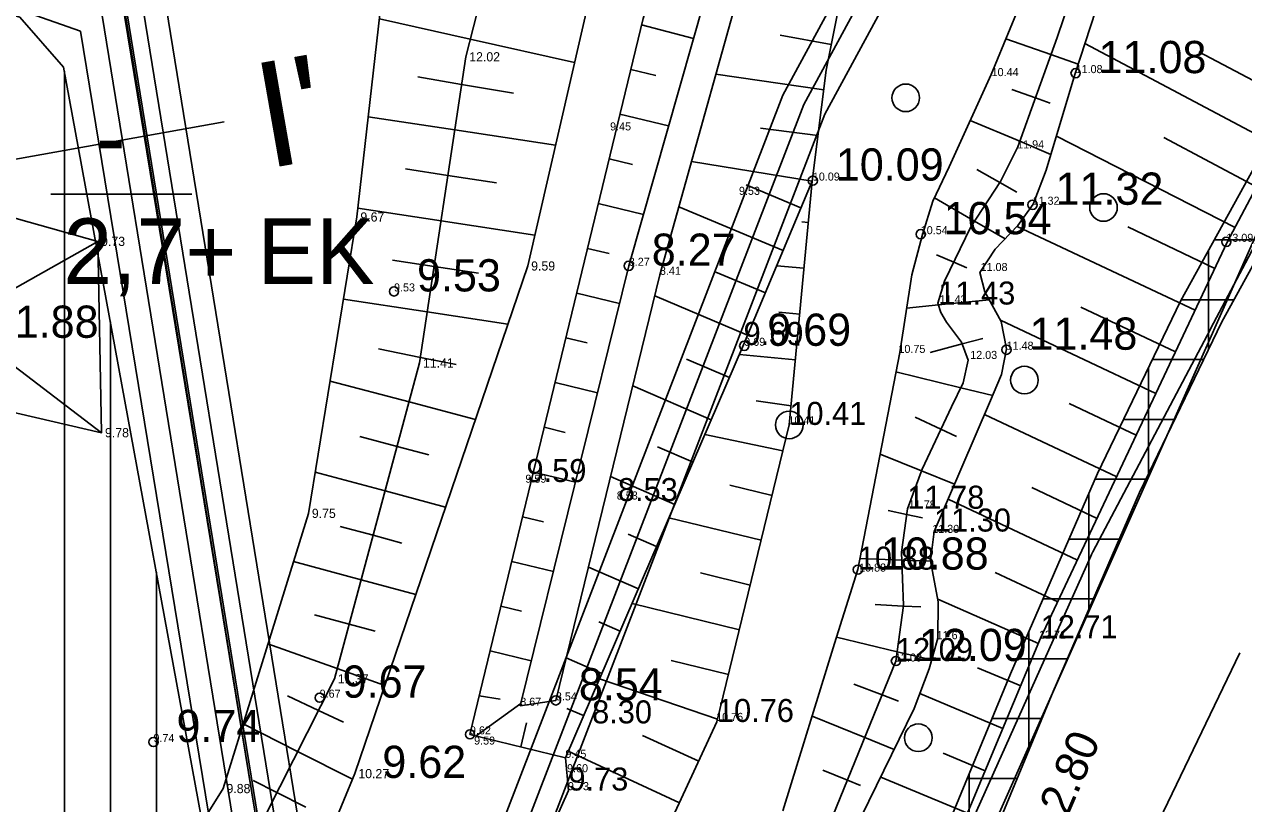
# Model space of a CAD drawing. Extents: x 433497 to 434382, y 6534486 to 6534993.
# Drawn here: x 434123.5 to 434176.5, y 6534820.5 to 6534854.4 of the extents above; entities that cross this region are included whole.
import ezdxf

# ---------------------------------------------------------------- set-up
doc = ezdxf.new("R2010")
doc.units = 0
for name, color, linetype in [('Default', 7, 'Continuous'), ('GEOLPUNKT', 7, 'Continuous'), ('HALJASTUS', 7, 'Continuous'), ('Kaitsevöönd', 7, 'Continuous'), ('kataster', 7, 'Continuous'), ('KORGUS-EH2000', 7, 'Continuous'), ('l__x00e4__bil__x00f5__iked', 7, 'Continuous'), ('MAAMUDEL-EH2000', 7, 'Continuous'), ('MOOTKORG-EH2000', 7, 'Continuous'), ('PIIR', 7, 'Continuous'), ('RELJEEF', 7, 'Continuous'), ('TEE', 7, 'Continuous'), ('Täide', 7, 'Continuous'), ('VEEKOGU', 7, 'Continuous')]:
    doc.layers.add(name, color=color, linetype=linetype)

msp = doc.modelspace()

# ---------------------------------------------------------------- linework, layer by layer
at = {"layer": 'Default'}
msp.add_lwpolyline([(433617.12, 6534791.025), (433632.75, 6534606.045), (434137.38, 6534796.515), (434127.69, 6534855.6), (433968.21, 6534911.925), (433942.38, 6534904.035), (433920.99, 6534907.275)], close=True, dxfattribs=at)
msp.add_lwpolyline([(433617.12, 6534791.025), (433632.75, 6534606.045), (434137.38, 6534796.515), (434127.69, 6534855.6), (433968.21, 6534911.925), (433942.38, 6534904.035), (433920.99, 6534907.275)], close=True, dxfattribs=at)
msp.add_lwpolyline([(433617.12, 6534791.025), (433632.75, 6534606.045), (434137.38, 6534796.515), (434127.69, 6534855.6), (433968.21, 6534911.925), (433942.38, 6534904.035), (433920.99, 6534907.275)], close=True, dxfattribs=at)
at = {"layer": 'GEOLPUNKT'}
msp.add_lwpolyline([(434124.622, 6534847.029), (434130.749, 6534847.029)], dxfattribs=at)
at = {"layer": 'HALJASTUS'}
msp.add_lwpolyline([(434176.296, 6534827.099), (434172.063, 6534818.302), (434169.946, 6534813.21), (434168.822, 6534810.233), (434168.64, 6534809.811), (434168.425, 6534809.332), (434168.425, 6534809.067), (434168.491, 6534808.72), (434168.468, 6534808.536), (434169.037, 6534808.042), (434171.153, 6534807.166), (434175.419, 6534805.557), (434176.131, 6534805.38), (434178.214, 6534804.983), (434182.414, 6534804.586), (434188.202, 6534804.421), (434190.149, 6534804.398), (434193.758, 6534804.388)], dxfattribs=at)
for centre in [(434161.779, 6534851.217), (434170.372, 6534846.452), (434166.935, 6534838.952), (434156.717, 6534837.003), (434162.326, 6534823.407)]:
    msp.add_circle(centre, 0.6, dxfattribs=at)
at = {"layer": 'Kaitsevöönd'}
for p, q in [((434175.189, 6534845.039), (434177.471, 6534845.039)), ((434174.931, 6534840.28), (434174.931, 6534844.571)), ((434173.755, 6534842.439), (434176.037, 6534842.439)), ((434172.331, 6534834.881), (434172.331, 6534839.489)), ((434172.499, 6534839.839), (434174.718, 6534839.839)), ((434171.247, 6534837.239), (434173.466, 6534837.239)), ((434170.007, 6534834.639), (434172.214, 6534834.639)), ((434169.731, 6534828.979), (434169.731, 6534834.002)), ((434168.879, 6534832.039), (434171.059, 6534832.039)), ((434167.751, 6534829.439), (434169.93, 6534829.439)), ((434167.131, 6534822.87), (434167.131, 6534828.01)), ((434166.623, 6534826.839), (434168.802, 6534826.839)), ((434165.534, 6534824.239), (434167.697, 6534824.239)), ((434164.458, 6534821.639), (434166.621, 6534821.639)), ((434164.531, 6534816.587), (434164.531, 6534821.816))]:
    msp.add_line(p, q, dxfattribs=at)
for points in [[(434128.222, 6534730.093), (434132.174, 6534738.642), (434136.032, 6534747.247), (434138.365, 6534752.329), (434142.93, 6534762.753), (434145.458, 6534769.142), (434146.369, 6534771.613), (434148.646, 6534776.777), (434150.916, 6534781.958), (434153.219, 6534787.206), (434154.721, 6534791.754), (434156.628, 6534795.899), (434159.877, 6534804.556), (434163.808, 6534814.841), (434168.182, 6534825.411), (434171.941, 6534834.072), (434175.51, 6534841.483), (434180.59, 6534850.694), (434185.974, 6534861.252), (434188.694, 6534866.232), (434193.777, 6534875.182), (434200.729, 6534887.95), (434203.323, 6534892.681)], [(434198.974, 6534888.909), (434192.024, 6534876.146), (434186.943, 6534867.198), (434184.199, 6534862.173), (434178.816, 6534851.617), (434173.72, 6534842.375), (434170.114, 6534834.886), (434166.338, 6534826.183), (434161.945, 6534815.568), (434158.005, 6534805.262), (434154.768, 6534796.635), (434152.881, 6534792.54), (434152.839, 6534792.435), (434151.335, 6534787.878), (434149.085, 6534782.762), (434146.815, 6534777.582), (434144.503, 6534772.334), (434143.585, 6534769.845), (434141.077, 6534763.506), (434136.537, 6534753.14), (434134.209, 6534748.069), (434130.352, 6534739.465)]]:
    msp.add_lwpolyline(points, dxfattribs=at)
at = {"layer": 'kataster'}
msp.add_lwpolyline([(433617.102, 6534791.002), (433632.769, 6534606.029), (434137.446, 6534796.469), (434127.827, 6534855.589), (433950.026, 6534918.39)], close=True, dxfattribs=at)
msp.add_lwpolyline([(434117.185, 6534708.296), (434124.427, 6534725.502), (434148.55, 6534781.242), (434178.983, 6534849.691), (434202.394, 6534892.23)], dxfattribs=at)
at = {"layer": 'KORGUS-EH2000'}
for centre in [(434169.16, 6534852.29), (434157.74, 6534847.62), (434167.29, 6534846.57), (434162.43, 6534845.29), (434175.71, 6534844.96), (434149.741, 6534843.917), (434139.54, 6534842.804), (434154.76, 6534840.44), (434166.16, 6534840.27), (434159.697, 6534830.713), (434161.352, 6534826.741), (434136.307, 6534825.149), (434146.573, 6534825.031), (434142.84, 6534823.556), (434129.085, 6534823.221)]:
    msp.add_circle(centre, 0.2, dxfattribs=at)
at = {"layer": 'l__x00e4__bil__x00f5__iked'}
msp.add_lwpolyline([(433620.07, 6534691.039), (433627.105, 6534692.187), (433736.834, 6534712.709), (433742.792, 6534710.723), (433822.234, 6534766.498), (433986.579, 6534812.177), (434120.472, 6534848.091), (434132.163, 6534850.175)], dxfattribs=at)
at = {"layer": 'PIIR'}
for points in [[(434138.342, 6534801.592), (434129.36, 6534856.88), (433968.248, 6534913.871)], [(433632.021, 6534604.835), (434138.248, 6534795.936), (434128.468, 6534856.135), (433968.226, 6534912.818), (433942.33, 6534904.85), (433920.952, 6534908.165), (433616.327, 6534791.524), (433632.021, 6534604.835)], [(433632.732, 6534605.959), (434137.353, 6534796.454), (434127.754, 6534855.539), (433968.208, 6534911.976), (433942.39, 6534904.031), (433921.04, 6534907.341), (433617.174, 6534790.992), (433632.732, 6534605.959)], [(434137.312, 6534801.699), (434156.44, 6534851.34), (434184.392, 6534902.877)], [(434138.342, 6534801.592), (434157.35, 6534850.92), (434185.271, 6534902.4)], [(434138.358, 6534798.853), (434158.26, 6534850.5), (434186.15, 6534901.923)]]:
    msp.add_lwpolyline(points, dxfattribs=at)
for points in [[(433618.234, 6534790.327), (433921.149, 6534906.313), (433942.464, 6534903.008), (433968.187, 6534910.923), (434126.862, 6534854.794), (434136.235, 6534797.101), (433633.617, 6534607.362)], [(433619.24, 6534789.695), (433634.52, 6534608.851), (434135.141, 6534797.808), (434125.908, 6534854.108), (433968.165, 6534909.82), (433942.53, 6534901.99), (433921.212, 6534905.219)], [(433619.24, 6534789.695), (433634.52, 6534608.851), (434135.141, 6534797.808), (434125.908, 6534854.108), (433968.165, 6534909.82), (433942.53, 6534901.99), (433921.212, 6534905.219)]]:
    msp.add_lwpolyline(points, close=True, dxfattribs=at)
at = {"layer": 'RELJEEF'}
for p, q in [((434142.855, 6534853.763), (434138.905, 6534854.647)), ((434150.299, 6534854.394), (434152.549, 6534853.793)), ((434156.328, 6534853.942), (434158.543, 6534853.534)), ((434168.088, 6534853.094), (434166.129, 6534853.788)), ((434142.855, 6534853.763), (434147.383, 6534852.751)), ((434177.965, 6534849.122), (434169.567, 6534853.577)), ((434168.088, 6534853.094), (434169.274, 6534852.673)), ((434174.522, 6534853.213), (434178.903, 6534850.889)), ((434150.923, 6534852.186), (434149.829, 6534852.451)), ((434158.212, 6534851.563), (434153.528, 6534852.252)), ((434140.568, 6534852.129), (434142.479, 6534851.802)), ((434144.733, 6534851.415), (434142.479, 6534851.802)), ((434166.387, 6534851.58), (434167.412, 6534851.211)), ((434168.05, 6534850.982), (434167.412, 6534851.211)), ((434142.18, 6534849.824), (434138.423, 6534850.392)), ((434149.359, 6534850.507), (434151.469, 6534849.996)), ((434166.736, 6534849.329), (434164.584, 6534850.235)), ((434142.18, 6534849.824), (434146.558, 6534849.162)), ((434155.46, 6534849.895), (434157.961, 6534849.579)), ((434176.091, 6534845.589), (434168.329, 6534849.557)), ((434166.736, 6534849.329), (434168.09, 6534848.759)), ((434172.991, 6534849.497), (434177.028, 6534847.356)), ((434149.905, 6534848.317), (434148.888, 6534848.563)), ((434140.039, 6534848.125), (434141.881, 6534847.847)), ((434157.71, 6534847.595), (434152.467, 6534848.448)), ((434164.866, 6534848.097), (434165.863, 6534847.532)), ((434143.995, 6534847.527), (434141.881, 6534847.847)), ((434154.843, 6534847.43), (434157.224, 6534846.433)), ((434157.71, 6534847.595), (434157.71, 6534847.595)), ((434166.604, 6534847.112), (434165.863, 6534847.532)), ((434141.582, 6534845.869), (434137.972, 6534846.415)), ((434148.418, 6534846.619), (434150.375, 6534846.146)), ((434156.452, 6534844.588), (434151.92, 6534846.485)), ((434164.769, 6534845.858), (434163.026, 6534846.864)), ((434141.582, 6534845.869), (434145.659, 6534845.253)), ((434157.263, 6534845.829), (434157.543, 6534845.803)), ((434164.769, 6534845.858), (434166.094, 6534845.092)), ((434174.355, 6534841.986), (434166.619, 6534845.631)), ((434171.423, 6534845.618), (434175.208, 6534843.795)), ((434120.494, 6534841.488), (434126.661, 6534844.978)), ((434148.888, 6534844.447), (434147.948, 6534844.675)), ((434163.114, 6534844.399), (434163.866, 6534844.075)), ((434139.475, 6534844.165), (434141.283, 6534843.892)), ((434143.214, 6534843.6), (434141.283, 6534843.892)), ((434157.356, 6534843.812), (434156.173, 6534843.923)), ((434164.434, 6534843.831), (434163.866, 6534844.075)), ((434153.529, 6534843.644), (434155.68, 6534842.743)), ((434147.478, 6534842.731), (434149.338, 6534842.281)), ((434140.984, 6534841.914), (434137.344, 6534842.464)), ((434154.907, 6534840.898), (434150.87, 6534842.608)), ((434163.198, 6534842.215), (434161.816, 6534842.075)), ((434163.198, 6534842.215), (434165.402, 6534842.44)), ((434169.388, 6534842.115), (434173.503, 6534840.177)), ((434140.984, 6534841.914), (434144.49, 6534841.384)), ((434156.267, 6534841.905), (434157.169, 6534841.821)), ((434120.494, 6534841.488), (434126.831, 6534836.665)), ((434172.651, 6534838.367), (434165.891, 6534841.552)), ((434147.933, 6534840.563), (434147.008, 6534840.787)), ((434165.125, 6534840.757), (434164.231, 6534840.522)), ((434138.868, 6534840.304), (434140.685, 6534839.936)), ((434156.982, 6534839.829), (434154.55, 6534840.057)), ((434162.84, 6534840.156), (434164.231, 6534840.522)), ((434142.234, 6534839.623), (434140.685, 6534839.936)), ((434152.257, 6534839.861), (434154.12, 6534839.06)), ((434164.167, 6534838.619), (434161.354, 6534839.303)), ((434140.192, 6534838), (434136.76, 6534838.899)), ((434146.538, 6534838.843), (434148.38, 6534838.397)), ((434153.327, 6534837.224), (434149.913, 6534838.697)), ((434164.167, 6534838.619), (434165.558, 6534838.28)), ((434140.192, 6534838), (434143.08, 6534837.243)), ((434155.283, 6534838.045), (434156.796, 6534837.838)), ((434168.882, 6534837.932), (434171.798, 6534836.558)), ((434170.946, 6534834.749), (434165.203, 6534837.454)), ((434146.984, 6534836.677), (434146.067, 6534836.899)), ((434162.193, 6534837.34), (434163.308, 6534836.812)), ((434138.055, 6534836.504), (434139.671, 6534836.069)), ((434156.443, 6534835.875), (434153.054, 6534836.591)), ((434163.98, 6534836.495), (434163.308, 6534836.812)), ((434141.049, 6534835.697), (434139.671, 6534836.069)), ((434150.983, 6534836.057), (434152.535, 6534835.387)), ((434162.456, 6534835.003), (434160.664, 6534835.727)), ((434139.151, 6534834.137), (434136.114, 6534834.956)), ((434145.597, 6534834.955), (434147.422, 6534834.514)), ((434151.742, 6534833.551), (434148.95, 6534834.756)), ((434162.456, 6534835.003), (434163.894, 6534834.423)), ((434154.131, 6534834.379), (434155.969, 6534833.932)), ((434167.251, 6534834.278), (434170.093, 6534832.94)), ((434139.151, 6534834.137), (434141.782, 6534833.429)), ((434169.241, 6534831.13), (434163.616, 6534833.78)), ((434161.021, 6534833.289), (434161.815, 6534833.115)), ((434162.507, 6534832.963), (434161.815, 6534833.115)), ((434137.197, 6534832.593), (434138.631, 6534832.206)), ((434146.035, 6534832.791), (434145.127, 6534833.011)), ((434155.496, 6534831.988), (434151.489, 6534832.964)), ((434139.883, 6534831.869), (434138.631, 6534832.206)), ((434149.709, 6534832.25), (434150.95, 6534831.715)), ((434138.11, 6534830.275), (434135.171, 6534831.067)), ((434144.657, 6534831.067), (434146.464, 6534830.63)), ((434161.607, 6534831.129), (434159.79, 6534831.196)), ((434161.607, 6534831.129), (434162.856, 6534831.084)), ((434150.158, 6534829.878), (434147.987, 6534830.815)), ((434152.854, 6534830.573), (434155.023, 6534830.045)), ((434165.667, 6534830.594), (434168.388, 6534829.321)), ((434138.11, 6534830.275), (434140.49, 6534829.634)), ((434167.546, 6534827.507), (434163.171, 6534829.437)), ((434145.086, 6534828.906), (434144.187, 6534829.123)), ((434154.549, 6534828.102), (434149.882, 6534829.239)), ((434160.453, 6534829.192), (434161.67, 6534829.131)), ((434162.43, 6534829.092), (434161.67, 6534829.131)), ((434136.084, 6534828.75), (434137.59, 6534828.344)), ((434138.717, 6534828.04), (434137.59, 6534828.344)), ((434148.435, 6534828.443), (434149.365, 6534828.042)), ((434137.069, 6534826.413), (434134.06, 6534827.485)), ((434161.406, 6534827.148), (434158.77, 6534827.775)), ((434143.716, 6534827.179), (434145.506, 6534826.746)), ((434148.573, 6534826.206), (434147.024, 6534826.874)), ((434151.577, 6534826.768), (434154.076, 6534826.159)), ((434161.406, 6534827.148), (434162.909, 6534826.791)), ((434137.069, 6534826.413), (434139.142, 6534825.675)), ((434164.903, 6534826.445), (434166.775, 6534825.662)), ((434153.603, 6534824.216), (434148.473, 6534825.975)), ((434159.517, 6534825.735), (434160.752, 6534825.269)), ((434134.908, 6534825.236), (434136.255, 6534824.595)), ((434144.154, 6534825.09), (434143.246, 6534825.235)), ((434161.461, 6534825.002), (434160.752, 6534825.269)), ((434166.003, 6534823.817), (434162.393, 6534825.326)), ((434143.104, 6534823.491), (434145.049, 6534824.891)), ((434147.056, 6534824.682), (434147.78, 6534824.369)), ((434137.339, 6534824.078), (434136.255, 6534824.595)), ((434159.999, 6534823.417), (434157.708, 6534824.349)), ((434135.352, 6534822.81), (434132.981, 6534824.008)), ((434145.304, 6534824.057), (434145.046, 6534823.012)), ((434150.338, 6534823.509), (434152.785, 6534822.393)), ((434159.999, 6534823.417), (434161.276, 6534822.897)), ((434135.352, 6534822.81), (434137.738, 6534821.604)), ((434151.944, 6534820.578), (434147.111, 6534822.818)), ((434151.944, 6534820.578), (434147.111, 6534822.818)), ((434163.402, 6534822.737), (434165.232, 6534821.972)), ((434158.18, 6534821.998), (434159.245, 6534821.564)), ((434133.415, 6534821.548), (434134.45, 6534821.025)), ((434159.819, 6534821.33), (434159.245, 6534821.564)), ((434164.46, 6534820.126), (434160.69, 6534821.702)), ((434135.711, 6534820.387), (434134.45, 6534821.025))]:
    msp.add_line(p, q, dxfattribs=at)
for points in [[(434146.988, 6534822.533), (434142.84, 6534823.556), (434150.364, 6534854.663), (434151.986, 6534860.051), (434159.289, 6534876.954), (434168.982, 6534892.451), (434176.303, 6534903.68)], [(434145.026, 6534824.798), (434149.741, 6534843.917), (434154.144, 6534859.405), (434161.15, 6534875.774), (434169.455, 6534890.171), (434178.472, 6534903.261)], [(434145.026, 6534824.798), (434146.573, 6534825.031), (434151.094, 6534843.526), (434155.48, 6534859.249), (434162.718, 6534874.963), (434170.742, 6534889.851), (434180.097, 6534902.569)], [(434157.71, 6534847.595), (434158.32, 6534852.418), (434160.207, 6534861.853), (434162.014, 6534868.117), (434164.505, 6534873.384), (434174.095, 6534889.798), (434181.01, 6534899.801)], [(434116.003, 6534779.573), (434118.33, 6534779.008), (434124.552, 6534778.351), (434128.388, 6534778.248), (434131.064, 6534778.414), (434134.99, 6534779.596), (434139.415, 6534780.978), (434142.65, 6534782.717), (434146.846, 6534785.714), (434149.957, 6534788.306), (434152.414, 6534790.827), (434154.555, 6534795.185), (434159.2, 6534807.543), (434167.641, 6534827.734), (434175.75, 6534844.947), (434185.846, 6534863.98), (434196.935, 6534884.171), (434200.713, 6534891.388)], [(434116.003, 6534779.573), (434118.33, 6534779.008), (434124.552, 6534778.351), (434128.388, 6534778.248), (434131.064, 6534778.414), (434134.99, 6534779.596), (434139.415, 6534780.978), (434142.65, 6534782.717), (434146.846, 6534785.714), (434149.957, 6534788.306), (434152.414, 6534790.827), (434154.555, 6534795.185), (434159.2, 6534807.543), (434167.641, 6534827.734), (434175.75, 6534844.947), (434185.846, 6534863.98), (434196.935, 6534884.171)], [(434177.736, 6534879.703), (434174.757, 6534874.572), (434169.627, 6534865.138), (434168.803, 6534863.153), (434167.859, 6534860.375), (434167.475, 6534858.022), (434166.863, 6534855.579), (434165.489, 6534852.229), (434163.666, 6534848.215), (434162.958, 6534846.721), (434162.51, 6534845.278), (434162.041, 6534843.524), (434161.517, 6534840.147), (434159.697, 6534830.713), (434158.687, 6534827.511), (434156.433, 6534820.225)], [(434126.192, 6534811.695), (434132.1, 6534807.95), (434137.84, 6534821.85), (434145.35, 6534843.91), (434148.595, 6534858.023), (434153.175, 6534872.071), (434151.226, 6534875.962), (434145.88, 6534874.56)], [(434145.88, 6534874.56), (434139.435, 6534859.319), (434137.93, 6534846.04), (434135.82, 6534833.16), (434132.11, 6534821.2), (434126.192, 6534811.695)], [(434147.81, 6534873.14), (434142.66, 6534853), (434140.649, 6534839.695), (434136.95, 6534825.97), (434131, 6534814.2)], [(434126.831, 6534836.665), (434126.661, 6534844.978), (434112.095, 6534849.077), (434095.482, 6534852.891), (434084.172, 6534855.488), (434070.619, 6534856.763), (434068.684, 6534851.354)], [(434155.559, 6534812.508), (434161.352, 6534826.741), (434161.674, 6534829.162), (434161.596, 6534831.468), (434161.848, 6534833.361), (434162.487, 6534835.085), (434163.771, 6534837.784), (434164.269, 6534838.833), (434164.496, 6534839.816), (434164.203, 6534840.595), (434163.548, 6534841.473), (434163.299, 6534841.892), (434163.172, 6534842.299), (434163.469, 6534843.255), (434164.61, 6534845.614), (434165.894, 6534847.579), (434166.648, 6534849.084), (434168.357, 6534853.843), (434168.96, 6534855.599)], [(434158.538, 6534817.308), (434162.146, 6534824.674), (434162.801, 6534826.404), (434163.172, 6534827.734), (434163.194, 6534829.313), (434162.854, 6534831.095), (434163.007, 6534832.368), (434165.422, 6534837.961), (434165.946, 6534839.193), (434166.151, 6534840.313), (434165.92, 6534841.499), (434165.212, 6534842.783), (434164.993, 6534843.623), (434165.658, 6534844.644), (434166.654, 6534845.666), (434167.31, 6534846.602), (434167.885, 6534848.077), (434169.13, 6534852.229), (434170.034, 6534855.022)], [(434068.684, 6534851.354), (434069.424, 6534849.76), (434083.306, 6534846.401), (434095.42, 6534843.47), (434108.17, 6534840.992), (434126.831, 6534836.665)], [(434113.19, 6534781.228), (434119.148, 6534781.228), (434129.078, 6534780.4), (434131.196, 6534780.65), (434133.547, 6534781.228), (434134.6, 6534782.717), (434135.868, 6534785.182), (434136.526, 6534787.186), (434139.174, 6534793.64), (434143.477, 6534801.419), (434147.284, 6534810.522), (434153.573, 6534824.093), (434156.717, 6534837.003), (434157.71, 6534847.595)], [(434146.988, 6534822.533), (434154.731, 6534840.478), (434157.71, 6534847.595), (434157.71, 6534847.595)], [(434138.05, 6534800.835), (434147.118, 6534821.114), (434146.988, 6534822.533)]]:
    msp.add_lwpolyline(points, dxfattribs=at)
at = {"layer": 'TEE'}
msp.add_lwpolyline([(434144.327, 6534780.781), (434148.542, 6534784.856), (434152.063, 6534787.177), (434164.597, 6534819.637), (434164.618, 6534819.688), (434164.64, 6534819.741), (434164.664, 6534819.795), (434169.822, 6534831.305), (434169.85, 6534831.366), (434169.88, 6534831.428), (434169.913, 6534831.492), (434175.016, 6534841.167), (434175.017, 6534841.169), (434175.019, 6534841.173), (434188.094, 6534865.834), (434188.111, 6534865.865), (434188.13, 6534865.899), (434188.15, 6534865.935), (434194.097, 6534876.248), (434200.82, 6534889.301), (434200.841, 6534889.341), (434200.864, 6534889.384), (434200.889, 6534889.428), (434202.717, 6534892.621)], dxfattribs=at)
at = {"layer": 'Täide'}
for p, q in [((434125.213, 6534794.516), (434125.213, 6534852.38)), ((434127.213, 6534795.211), (434127.213, 6534841.489)), ((434129.213, 6534795.906), (434129.213, 6534830.597))]:
    msp.add_line(p, q, dxfattribs=at)
msp.add_lwpolyline([(434053.953, 6534766.741), (434062.043, 6534770.897), (434076.601, 6534775.79), (434083.107, 6534779.636), (434100.67, 6534785.732), (434110.817, 6534789.511), (434130.115, 6534796.22), (434132.899, 6534799.258), (434133.017, 6534809.88), (434125.182, 6534852.548), (434123.278, 6534854.722), (434098.113, 6534862.108), (434062.901, 6534875.407), (434022.093, 6534888.443), (434021.059, 6534887.256), (434037.893, 6534864.165), (434021.392, 6534791.18), (434023.3, 6534781.148), (434025.663, 6534773.898), (434039.607, 6534770.357), (434045.083, 6534767.989), (434045.714, 6534765.502), (434044.882, 6534761.539)], dxfattribs=at)
at = {"layer": 'VEEKOGU'}
msp.add_lwpolyline([(434169.455, 6534890.171), (434159.61, 6534874.859), (434154.144, 6534859.405), (434149.741, 6534843.917), (434145.026, 6534824.798), (434146.573, 6534825.031), (434151.094, 6534843.526), (434155.48, 6534859.249), (434162.718, 6534874.963), (434170.742, 6534889.851), (434180.097, 6534902.569)], dxfattribs=at)

# ---------------------------------------------------------------- texts
at = {"layer": 'GEOLPUNKT'}
for s, p in [('-', (434126.598, 6534848.091)), ('2,7+', (434125.168, 6534843.126)), ('EK', (434133.609, 6534843.126))]:
    msp.add_text(s, height=2.85, dxfattribs=at).set_placement(p)
at = {"layer": 'KORGUS-EH2000'}
for s, p in [('11.08', (434170.16, 6534852.29)), ('10.09', (434158.74, 6534847.62)), ('11.32', (434168.29, 6534846.57)), ('10.54', (434163.43, 6534845.29)), ('8.27', (434150.741, 6534843.917)), ('9.53', (434140.54, 6534842.804)), (' 11.88', (434121.494, 6534840.788)), ('9.69', (434155.76, 6534840.44)), ('11.48', (434167.16, 6534840.27)), ('10.88', (434160.697, 6534830.713)), ('12.09', (434162.352, 6534826.741)), ('9.67', (434137.307, 6534825.149)), ('8.54', (434147.573, 6534825.031)), ('9.74', (434130.085, 6534823.221)), ('9.62', (434139.032, 6534821.661))]:
    msp.add_text(s, height=1.4, dxfattribs=at).set_placement(p)
msp.add_text('12.80', height=1.4, rotation=66.7748, dxfattribs=at).set_placement((434168.409, 6534818.995))
at = {"layer": 'l__x00e4__bil__x00f5__iked'}
msp.add_text("I'", height=4.58, rotation=9.9407, dxfattribs=at).set_placement((434134.009, 6534848.134))
at = {"layer": 'MAAMUDEL-EH2000'}
for s, p in [(' 12.02', (434142.66, 6534852.8)), (' 9.67', (434137.93, 6534845.84)), (' 9.73', (434126.661, 6534844.778)), (' 9.59', (434145.35, 6534843.71)), (' 11.41', (434140.649, 6534839.495)), (' 9.78', (434126.831, 6534836.465)), (' 9.78', (434126.831, 6534836.465)), (' 9.75', (434135.82, 6534832.96)), (' 11.37', (434136.95, 6534825.77)), (' 10.27', (434137.84, 6534821.65)), (' 9.88', (434132.11, 6534821))]:
    msp.add_text(s, height=0.4, dxfattribs=at).set_placement(p)
at = {"layer": 'MOOTKORG-EH2000'}
for s, height, p in [('10.44', 0.35, (434165.51, 6534852.16)), ('11.08', 0.35, (434169.16, 6534852.29)), ('9.45', 0.35, (434148.93, 6534849.8)), ('11.94', 0.35, (434166.62, 6534849.02)), ('10.09', 0.35, (434157.74, 6534847.62)), ('9.53', 0.35, (434154.53, 6534847)), ('11.32', 0.35, (434167.29, 6534846.57)), ('10.54', 0.35, (434162.43, 6534845.29)), ('13.09', 0.35, (434175.71, 6534844.96)), ('8.27', 0.35, (434149.741, 6534843.917)), ('8.41', 0.35, (434151.094, 6534843.526)), ('11.08', 0.35, (434165.03, 6534843.69)), ('11.43', 1, (434163.192, 6534842.234)), ('9.53', 0.35, (434139.54, 6534842.804)), ('11.43', 0.35, (434163.25, 6534842.29)), ('9.69', 1, (434154.731, 6534840.478)), ('9.69', 0.35, (434154.76, 6534840.44)), ('11.48', 0.35, (434166.16, 6534840.27)), ('10.75', 0.35, (434161.46, 6534840.13)), ('12.03', 0.35, (434164.58, 6534839.87)), ('10.41', 1, (434156.717, 6534837.003)), ('10.41', 0.35, (434156.68, 6534837.03)), ('9.59', 1, (434145.298, 6534834.52)), ('9.59', 0.35, (434145.25, 6534834.49)), ('8.53', 1, (434149.27, 6534833.692)), ('11.78', 1, (434161.848, 6534833.361)), ('8.53', 0.35, (434149.22, 6534833.76)), ('11.78', 0.35, (434161.91, 6534833.37)), ('11.30', 1, (434163.007, 6534832.368)), ('11.30', 0.35, (434162.93, 6534832.31)), ('10.88', 1, (434159.697, 6534830.713)), ('10.88', 0.35, (434159.75, 6534830.63)), ('12.71', 1, (434167.641, 6534827.734)), ('11.67', 0.35, (434163.12, 6534827.69)), ('12.71', 0.35, (434167.57, 6534827.71)), ('12.09', 1, (434161.352, 6534826.741)), ('12.09', 0.35, (434161.31, 6534826.72)), ('9.67', 0.35, (434136.307, 6534825.149)), ('8.54', 0.35, (434146.573, 6534825.031)), ('8.67', 0.35, (434145.026, 6534824.798)), ('8.30', 1, (434148.149, 6534824.032)), ('10.76', 1, (434153.573, 6534824.093)), ('10.76', 0.35, (434153.54, 6534824.14)), ('9.74', 0.35, (434129.085, 6534823.221)), ('9.62', 0.35, (434142.84, 6534823.556)), ('9.59', 0.35, (434143.02, 6534823.11)), ('9.45', 0.35, (434146.988, 6534822.533)), ('9.60', 0.35, (434147.06, 6534821.91)), ('9.73', 1, (434147.118, 6534821.114)), ('9.73', 0.35, (434147.1, 6534821.13))]:
    msp.add_text(s, height=height, dxfattribs=at).set_placement(p)

doc.saveas('drawing.dxf')
